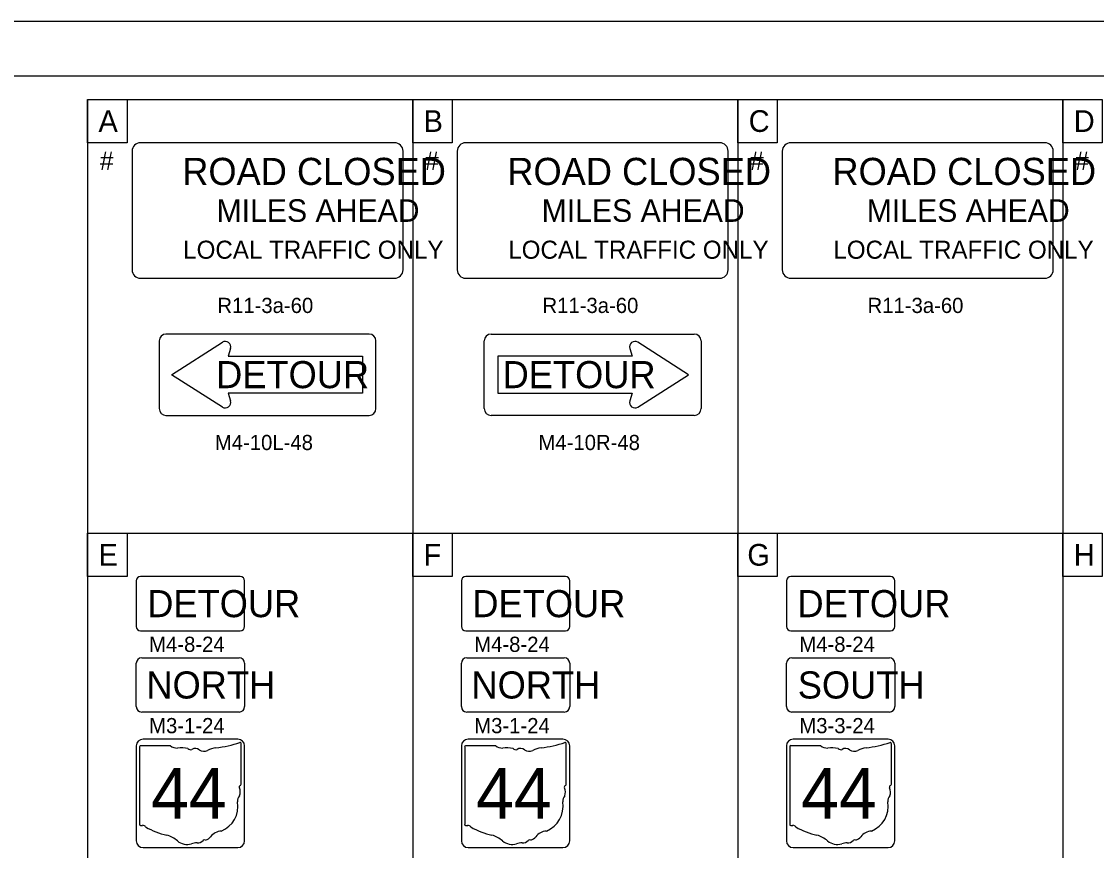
# Model space of a CAD drawing. Extents: x 0 to 34, y 0 to 22.
# Drawn here: x 19.09 to 29.01, y 14.36 to 22 of the extents above; entities that cross this region are included whole.
import ezdxf

# ---------------------------------------------------------------- set-up
doc = ezdxf.new("R2010")
doc.units = 0
for name, color, linetype in [('SC_Scratch1', 7, 'Continuous'), ('SH_Border', 7, 'Continuous'), ('SH_Cut_Line', 7, 'Continuous'), ('SH_Text', 7, 'Continuous'), ('SN_P_Signs', 7, 'Continuous'), ('SN_P_Text', 7, 'Continuous')]:
    doc.layers.add(name, color=color, linetype=linetype)

msp = doc.modelspace()

# ---------------------------------------------------------------- linework, layer by layer
at = {"layer": 'SC_Scratch1'}
for p, q in [((19.7007, 21.2819), (28.7007, 21.2819)), ((19.7007, 21.2819), (19.7007, 3.1937)), ((22.7007, 21.2819), (22.7007, 3.1937)), ((25.7007, 21.2819), (25.7007, 3.1937)), ((28.7007, 21.2819), (28.7007, 3.1937)), ((19.7007, 17.2819), (28.7007, 17.2819))]:
    msp.add_line(p, q, dxfattribs=at)
at = {"layer": 'SH_Border'}
msp.add_lwpolyline([(1.5, 21.5), (33.5, 21.5), (33.5, 0.5), (1.5, 0.5)], close=True, dxfattribs=at)
at = {"layer": 'SH_Cut_Line'}
msp.add_lwpolyline([(0, 0), (34, 0), (34, 22), (0, 22)], close=True, dxfattribs=at)
at = {"layer": 'SH_Text'}
for points in [[(19.7007, 21.2819), (20.0642, 21.2819), (20.0642, 20.8819), (19.7007, 20.8819)], [(22.7007, 21.2819), (23.0642, 21.2819), (23.0642, 20.8819), (22.7007, 20.8819)], [(25.7007, 21.2819), (26.0642, 21.2819), (26.0642, 20.8819), (25.7007, 20.8819)], [(28.7007, 21.2819), (29.0642, 21.2819), (29.0642, 20.8819), (28.7007, 20.8819)], [(19.7007, 17.2819), (20.0642, 17.2819), (20.0642, 16.8819), (19.7007, 16.8819)], [(22.7007, 17.2819), (23.0642, 17.2819), (23.0642, 16.8819), (22.7007, 16.8819)], [(25.7007, 17.2819), (26.0642, 17.2819), (26.0642, 16.8819), (25.7007, 16.8819)], [(28.7007, 17.2819), (29.0642, 17.2819), (29.0642, 16.8819), (28.7007, 16.8819)]]:
    msp.add_lwpolyline(points, close=True, dxfattribs=at)
at = {"layer": 'SN_P_Signs'}
for p, q in [((20.4758, 18.743), (20.9444, 19.0417)), ((21.0189, 18.9843), (20.9966, 18.9149)), ((24.7035, 18.9843), (24.7258, 18.9149)), ((25.2466, 18.743), (24.778, 19.0417)), ((20.9966, 18.9149), (22.2362, 18.9149)), ((22.2362, 18.9149), (22.2362, 18.5712)), ((24.7258, 18.9149), (23.4862, 18.9149)), ((23.4862, 18.9149), (23.4862, 18.5712)), ((20.9444, 18.4443), (20.4758, 18.743)), ((24.778, 18.4443), (25.2466, 18.743)), ((22.2362, 18.5712), (20.9966, 18.5712)), ((20.9966, 18.5712), (21.0189, 18.5018)), ((23.4862, 18.5712), (24.7258, 18.5712)), ((24.7258, 18.5712), (24.7035, 18.5018)), ((20.1493, 15.6819), (20.1493, 16.0819)), ((20.1993, 16.1319), (21.0993, 16.1319)), ((21.1493, 16.0819), (21.1493, 15.6819)), ((23.1493, 15.6819), (23.1493, 16.0819)), ((23.1993, 16.1319), (24.0993, 16.1319)), ((24.1493, 16.0819), (24.1493, 15.6819)), ((26.1493, 15.6818), (26.1493, 16.0818)), ((26.1993, 16.1318), (27.0993, 16.1318)), ((27.1493, 16.0818), (27.1493, 15.6818)), ((21.0993, 15.6319), (20.1993, 15.6319)), ((24.0993, 15.6319), (23.1993, 15.6319)), ((27.0993, 15.6318), (26.1993, 15.6318)), ((20.1799, 15.3098), (20.1799, 14.5982)), ((20.4636, 15.322), (20.1891, 15.322)), ((21.1173, 14.9674), (21.1173, 15.3397)), ((23.1799, 15.3098), (23.1799, 14.5982)), ((23.4636, 15.322), (23.1891, 15.322)), ((24.1173, 14.9674), (24.1173, 15.3397)), ((26.1799, 15.3098), (26.1799, 14.5982)), ((26.4636, 15.322), (26.1891, 15.322)), ((27.1173, 14.9674), (27.1173, 15.3397)), ((21.1172, 14.9675), (21.1173, 14.9674)), ((24.1172, 14.9675), (24.1173, 14.9674)), ((27.1172, 14.9675), (27.1173, 14.9674))]:
    msp.add_line(p, q, dxfattribs=at)
for points in [[(22.5331, 20.8819), (20.1893, 20.8819)], [(25.5331, 20.8819), (23.1893, 20.8819)], [(28.5331, 20.8819), (26.1893, 20.8819)], [(20.1112, 20.8037), (20.1112, 19.71)], [(22.6112, 19.71), (22.6112, 20.8037)], [(23.1112, 20.8037), (23.1112, 19.71)], [(25.6112, 19.71), (25.6112, 20.8037)], [(26.1112, 20.8037), (26.1112, 19.71)], [(28.6112, 19.71), (28.6112, 20.8037)], [(20.1893, 19.6319), (22.5331, 19.6319)], [(23.1893, 19.6319), (25.5331, 19.6319)], [(26.1893, 19.6319), (28.5331, 19.6319)], [(20.3612, 19.0555), (20.3612, 18.4305)], [(22.2987, 19.118), (20.4237, 19.118)], [(22.3612, 18.4305), (22.3612, 19.0555)], [(23.3612, 18.4305), (23.3612, 19.0555)], [(23.4237, 19.118), (25.2987, 19.118)], [(25.3612, 19.0555), (25.3612, 18.4305)], [(20.4237, 18.368), (22.2987, 18.368)], [(25.2987, 18.368), (23.4237, 18.368)], [(21.1093, 16.8819), (20.1893, 16.8819)], [(24.1093, 16.8819), (23.1893, 16.8819)], [(27.1093, 16.8819), (26.1893, 16.8819)], [(20.1493, 16.8419), (20.1493, 16.4219)], [(21.1493, 16.4219), (21.1493, 16.8419)], [(23.1493, 16.8419), (23.1493, 16.4219)], [(24.1493, 16.4219), (24.1493, 16.8419)], [(26.1493, 16.8419), (26.1493, 16.4219)], [(27.1493, 16.4219), (27.1493, 16.8419)], [(20.1893, 16.3819), (21.1093, 16.3819)], [(23.1893, 16.3819), (24.1093, 16.3819)], [(26.1893, 16.3819), (27.1093, 16.3819)], [(21.0868, 15.3819), (20.2118, 15.3819)], [(24.0868, 15.3819), (23.2118, 15.3819)], [(27.0868, 15.3819), (26.2118, 15.3819)], [(20.1493, 15.3194), (20.1493, 14.4443)], [(21.1493, 14.4443), (21.1493, 15.3194)], [(23.1493, 15.3194), (23.1493, 14.4443)], [(24.1493, 14.4443), (24.1493, 15.3194)], [(26.1493, 15.3194), (26.1493, 14.4443)], [(27.1493, 14.4443), (27.1493, 15.3194)], [(20.2118, 14.3818), (21.0868, 14.3818)], [(23.2118, 14.3818), (24.0868, 14.3818)], [(26.2118, 14.3818), (27.0868, 14.3818)]]:
    msp.add_lwpolyline(points, dxfattribs=at)
for centre, radius, start, end in [((20.1893, 20.8037), 0.0781, 90, 180), ((22.5331, 20.8037), 0.0781, 0, 90), ((23.1893, 20.8037), 0.0781, 90, 180), ((25.5331, 20.8037), 0.0781, 0, 90), ((26.1893, 20.8037), 0.0781, 90, 180), ((28.5331, 20.8037), 0.0781, 0, 90), ((20.1893, 19.71), 0.0781, 180, 270), ((22.5331, 19.71), 0.0781, 270, 0), ((23.1893, 19.71), 0.0781, 180, 270), ((25.5331, 19.71), 0.0781, 270, 0), ((26.1893, 19.71), 0.0781, 180, 270), ((28.5331, 19.71), 0.0781, 270, 0), ((20.4237, 19.0555), 0.0625, 90, 180), ((20.9713, 18.9996), 0.05, 342.18111, 122.51085), ((22.2987, 19.0555), 0.0625, 0, 90), ((23.4237, 19.0555), 0.0625, 90, 180), ((24.7511, 18.9996), 0.05, 57.48915, 197.81889), ((25.2987, 19.0555), 0.0625, 0, 90), ((20.9713, 18.4865), 0.05, 237.48915, 17.81889), ((24.7511, 18.4865), 0.05, 162.18111, 302.51085), ((20.4237, 18.4305), 0.0625, 180, 270), ((22.2987, 18.4305), 0.0625, 270, 0), ((23.4237, 18.4305), 0.0625, 180, 270), ((25.2987, 18.4305), 0.0625, 270, 360), ((20.1893, 16.8419), 0.04, 90, 180), ((21.1093, 16.8419), 0.04, 0, 90), ((23.1893, 16.8419), 0.04, 90, 180), ((24.1093, 16.8419), 0.04, 0, 90), ((26.1893, 16.8419), 0.04, 90, 180), ((27.1093, 16.8419), 0.04, 0, 90), ((20.1893, 16.4219), 0.04, 180, 270), ((21.1093, 16.4219), 0.04, 270, 0), ((23.1893, 16.4219), 0.04, 180, 270), ((24.1093, 16.4219), 0.04, 270, 0), ((26.1893, 16.4219), 0.04, 180, 270), ((27.1093, 16.4219), 0.04, 270, 0), ((20.1993, 16.0818), 0.05, 90, 180), ((21.0993, 16.0818), 0.05, 0, 90), ((23.1993, 16.0818), 0.05, 90, 180), ((24.0993, 16.0818), 0.05, 0, 90), ((26.1993, 16.0818), 0.05, 90, 180), ((27.0993, 16.0818), 0.05, 0, 90), ((20.1993, 15.6818), 0.05, 180, 270), ((21.0993, 15.6818), 0.05, 270, 0), ((23.1993, 15.6818), 0.05, 180, 270), ((24.0993, 15.6818), 0.05, 270, 0), ((26.1993, 15.6818), 0.05, 180, 270), ((27.0993, 15.6818), 0.05, 270, 0), ((20.2118, 15.3194), 0.0625, 90, 180), ((21.0868, 15.3194), 0.0625, 0, 90), ((23.2118, 15.3194), 0.0625, 90, 180), ((24.0868, 15.3194), 0.0625, 0, 90), ((26.2118, 15.3194), 0.0625, 90, 180), ((27.0868, 15.3194), 0.0625, 0, 90), ((20.1906, 15.3113), 0.0109, 98.1301, 188.1301), ((20.529, 15.4046), 0.1053, 231.61951, 271.11188), ((20.5639, 14.9226), 0.3782, 80.48669, 94.98827), ((20.6498, 15.315), 0.0304, 219.79206, 297.10237), ((20.6944, 15.2328), 0.0632, 54.46668, 119.14113), ((20.776, 15.3455), 0.076, 233.85621, 294.82819), ((20.9102, 15.1047), 0.2, 97.34618, 120.76885), ((20.7834, 16.2921), 0.9942, 275.84447, 288.90645), ((21.1069, 15.3412), 0.0104, 351.86209, 97.738), ((23.1906, 15.3113), 0.0109, 98.1301, 188.1301), ((23.529, 15.4046), 0.1053, 231.61951, 271.11188), ((23.5639, 14.9226), 0.3782, 80.48669, 94.98827), ((23.6498, 15.315), 0.0304, 219.79206, 297.10237), ((23.6944, 15.2328), 0.0632, 54.46668, 119.14113), ((23.776, 15.3455), 0.076, 233.85621, 294.82819), ((23.9102, 15.1047), 0.2, 97.34618, 120.76885), ((23.7834, 16.2921), 0.9942, 275.84447, 288.90645), ((24.1069, 15.3412), 0.0104, 351.86209, 97.738), ((26.1906, 15.3113), 0.0109, 98.1301, 188.1301), ((26.529, 15.4046), 0.1053, 231.61951, 271.11188), ((26.5639, 14.9226), 0.3782, 80.48669, 94.98827), ((26.6498, 15.315), 0.0304, 219.79206, 297.10237), ((26.6944, 15.2328), 0.0632, 54.46668, 119.14113), ((26.776, 15.3455), 0.076, 233.85621, 294.82819), ((26.9102, 15.1047), 0.2, 97.34618, 120.76885), ((26.7834, 16.2921), 0.9942, 275.84447, 288.90645), ((27.1069, 15.3412), 0.0104, 351.86209, 97.738), ((21.1149, 14.9401), 0.0162, 107.94398, 210.33697), ((21.0122, 14.8931), 0.097, 340.03296, 23.64957), ((21.1062, 14.966), 0.0112, 289.60381, 7.73413), ((24.1149, 14.9401), 0.0162, 107.94398, 210.33697), ((24.0122, 14.8931), 0.097, 340.03296, 23.64957), ((24.1062, 14.966), 0.0112, 289.60381, 7.73413), ((27.1149, 14.9401), 0.0162, 107.94398, 210.33697), ((27.0122, 14.8931), 0.097, 340.03296, 23.64957), ((27.1062, 14.966), 0.0112, 289.60381, 7.73413), ((20.8391, 14.7643), 0.2487, 292.30889, 8.98584), ((21.1547, 14.8117), 0.0705, 136.8065, 186.92959), ((23.8391, 14.7643), 0.2487, 292.30889, 8.98584), ((24.1547, 14.8117), 0.0705, 136.8065, 186.92959), ((26.8391, 14.7643), 0.2487, 292.30889, 8.98584), ((27.1547, 14.8117), 0.0705, 136.8065, 186.92959), ((20.1907, 14.5967), 0.011, 171.95839, 258.30661), ((20.1924, 14.6695), 0.0836, 267.33899, 280.60386), ((20.2095, 14.5572), 0.0302, 29.74838, 93.27175), ((23.1907, 14.5967), 0.011, 171.95839, 258.30661), ((23.1924, 14.6695), 0.0836, 267.33899, 280.60386), ((23.2095, 14.5572), 0.0302, 29.74838, 93.27175), ((26.1907, 14.5967), 0.011, 171.95839, 258.30661), ((26.1924, 14.6695), 0.0836, 267.33899, 280.60386), ((26.2095, 14.5572), 0.0302, 29.74838, 93.27175), ((20.5901, 15.1965), 0.7179, 240.41292, 257.1985), ((20.3761, 14.2786), 0.2246, 47.18416, 75.83597), ((20.9439, 14.3985), 0.1362, 94.40312, 142.57675), ((23.5901, 15.1965), 0.7179, 240.41292, 257.1985), ((23.3761, 14.2786), 0.2246, 47.18416, 75.83597), ((23.9439, 14.3985), 0.1362, 94.40312, 142.57675), ((26.5901, 15.1965), 0.7179, 240.41292, 257.1985), ((26.3761, 14.2786), 0.2246, 47.18416, 75.83597), ((26.9439, 14.3985), 0.1362, 94.40312, 142.57675), ((20.2118, 14.4443), 0.0625, 180, 270), ((20.619, 14.5537), 0.1425, 230.70037, 286.29184), ((20.7014, 14.3077), 0.1171, 85.69512, 111.20995), ((20.7118, 14.5004), 0.0759, 268.77702, 315.54927), ((20.7805, 14.4315), 0.0214, 65.75173, 132.64842), ((20.7714, 14.5293), 0.0803, 282.87319, 323.27711), ((21.0868, 14.4443), 0.0625, 270, 0), ((23.2118, 14.4443), 0.0625, 180, 270), ((23.619, 14.5537), 0.1425, 230.70037, 286.29184), ((23.7014, 14.3077), 0.1171, 85.69512, 111.20995), ((23.7118, 14.5004), 0.0759, 268.77702, 315.54927), ((23.7805, 14.4315), 0.0214, 65.75173, 132.64842), ((23.7714, 14.5293), 0.0803, 282.87319, 323.27711), ((24.0868, 14.4443), 0.0625, 270, 0), ((26.2118, 14.4443), 0.0625, 180, 270), ((26.619, 14.5537), 0.1425, 230.70037, 286.29184), ((26.7014, 14.3077), 0.1171, 85.69512, 111.20995), ((26.7118, 14.5004), 0.0759, 268.77702, 315.54927), ((26.7805, 14.4315), 0.0214, 65.75173, 132.64842), ((26.7714, 14.5293), 0.0803, 282.87319, 323.27711), ((27.0868, 14.4443), 0.0625, 270, 0)]:
    msp.add_arc(centre, radius, start, end, dxfattribs=at)

# ---------------------------------------------------------------- texts
at = {"layer": 'SH_Text'}
for s, height, p in [('A', 0.2, (19.8007, 20.9819)), ('B', 0.2, (22.8007, 20.9819)), ('C', 0.2, (25.8007, 20.9819)), ('D', 0.2, (28.8007, 20.9819)), ('#', 0.17, (19.8136, 20.6305)), ('#', 0.17, (22.8136, 20.6305)), ('#', 0.17, (25.8136, 20.6305)), ('#', 0.17, (28.8136, 20.6305)), ('E', 0.2, (19.8007, 16.9819)), ('F', 0.2, (22.8007, 16.9819)), ('G', 0.2, (25.7884, 16.9819)), ('H', 0.2, (28.8007, 16.9819))]:
    msp.add_text(s, height=height, dxfattribs=at).set_placement(p)
at = {"layer": 'SN_P_Signs'}
for s, height, p in [('ROAD CLOSED', 0.25, (20.5734, 20.4928)), ('ROAD CLOSED', 0.25, (23.5734, 20.4928)), ('ROAD CLOSED', 0.25, (26.5734, 20.4928)), ('MILES AHEAD', 0.208333, (20.89, 20.1526)), ('MILES AHEAD', 0.208333, (23.89, 20.1526)), ('MILES AHEAD', 0.208333, (26.89, 20.1526)), ('LOCAL TRAFFIC ONLY', 0.166667, (20.5822, 19.8123)), ('LOCAL TRAFFIC ONLY', 0.166667, (23.5822, 19.8123)), ('LOCAL TRAFFIC ONLY', 0.166667, (26.5822, 19.8123)), ('DETOUR', 0.25, (20.8865, 18.6188)), ('DETOUR', 0.25, (23.5303, 18.6188)), ('DETOUR', 0.25, (20.2509, 16.5069)), ('DETOUR', 0.25, (23.2509, 16.5069)), ('DETOUR', 0.25, (26.2509, 16.5069)), ('NORTH', 0.25, (20.2427, 15.7568)), ('NORTH', 0.25, (23.2427, 15.7568)), ('SOUTH', 0.25, (26.2537, 15.7568)), ('44', 0.46875, (20.2858, 14.6484)), ('44', 0.46875, (23.2858, 14.6484)), ('44', 0.46875, (26.2858, 14.6484))]:
    msp.add_text(s, height=height, dxfattribs=at).set_placement(p)
at = {"layer": 'SN_P_Text'}
for s, p in [('R11-3a-60', (20.8979, 19.3119)), ('R11-3a-60', (23.8979, 19.3119)), ('R11-3a-60', (26.8979, 19.3119)), ('M4-10L-48', (20.8745, 18.048)), ('M4-10R-48', (23.8609, 18.048)), ('M4-8-24', (20.268, 16.1869)), ('M4-8-24', (23.268, 16.1869)), ('M4-8-24', (26.268, 16.1869)), ('M3-1-24', (20.268, 15.4369)), ('M3-1-24', (23.268, 15.4369)), ('M3-3-24', (26.268, 15.4368))]:
    msp.add_text(s, height=0.14, dxfattribs=at).set_placement(p)

doc.saveas('drawing.dxf')
